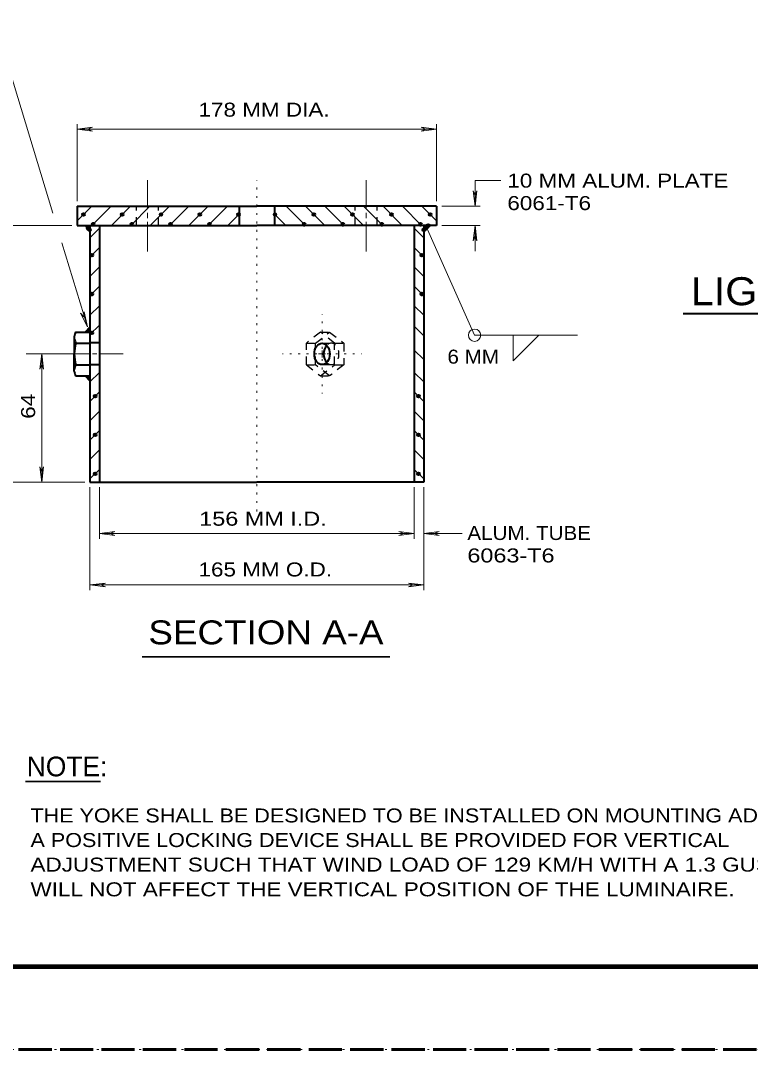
# Model space of a CAD drawing. Extents: x 312583 to 312854, y 144419 to 144597.
# Drawn here: x 312643.1 to 312682.7, y 144418.6 to 144474.4 of the extents above; entities that cross this region are included whole.
import ezdxf
from ezdxf.enums import TextEntityAlignment as Align

# ---------------------------------------------------------------- set-up
doc = ezdxf.new("R2010")
doc.units = 0
doc.header["$LTSCALE"] = 0.3
doc.header["$PDMODE"] = 32
doc.header["$PDSIZE"] = 0.15
for name, pattern in [('DOTTED', [1.5, 0.3, -1.2]), ('LONG_DASHED', [7.5, 6, -1.5]), ('SHORT_DASHED', [2.7, 1.5, -1.2])]:
    doc.linetypes.add(name, pattern=pattern)
for name, color, linetype, lineweight in [('1', 7, 'Continuous', 40), ('2', 7, 'Continuous', 13), ('63', 7, 'DOTTED', 13)]:
    doc.layers.add(name, color=color, linetype=linetype, lineweight=lineweight)

msp = doc.modelspace()

# ---------------------------------------------------------------- linework, layer by layer
at = {"layer": '1', "linetype": 'DOTTED', "lineweight": 13}
msp.add_line((312655.8787, 144447.7894), (312655.8787, 144465.7601), dxfattribs=at)
at = {"layer": '1'}
for p, q in [((312646.1267, 144464.3571), (312655.8787, 144464.3571)), ((312646.1267, 144464.3571), (312646.1267, 144463.3144)), ((312654.9204, 144464.3571), (312654.9204, 144463.3144)), ((312665.6384, 144464.3571), (312655.8787, 144464.3571)), ((312656.8447, 144464.3571), (312656.8447, 144463.3144)), ((312665.6384, 144464.3571), (312665.6384, 144463.3144)), ((312646.1267, 144463.3144), (312655.8787, 144463.3144)), ((312647.3381, 144463.3144), (312647.3381, 144449.3764)), ((312665.6384, 144463.3144), (312655.8787, 144463.3144)), ((312664.4194, 144463.3144), (312664.4194, 144449.3764)), ((312645.9734, 144457.2654), (312645.9734, 144456.3454)), ((312646.0577, 144457.5261), (312646.8167, 144457.5261)), ((312646.0654, 144456.9281), (312646.8167, 144456.9281)), ((312647.3381, 144456.9434), (312646.8167, 144456.9434)), ((312645.9734, 144455.4101), (312645.9734, 144456.3684)), ((312646.0577, 144455.7474), (312646.8167, 144455.7474)), ((312647.3381, 144455.7474), (312646.8167, 144455.7474)), ((312646.0577, 144455.1494), (312646.8167, 144455.1494)), ((312646.8167, 144449.3764), (312655.8787, 144449.3764)), ((312664.9407, 144449.3764), (312655.8787, 144449.3764))]:
    msp.add_line(p, q, dxfattribs=at)
at = {"layer": '1', "lineweight": 25}
for p, q in [((312646.1267, 144463.5597), (312646.9241, 144464.3571)), ((312646.9317, 144463.3144), (312647.9821, 144464.3571)), ((312647.9897, 144463.3144), (312649.0324, 144464.3571)), ((312649.0401, 144463.3144), (312650.0827, 144464.3571)), ((312650.0981, 144463.3144), (312651.1407, 144464.3571)), ((312651.1407, 144463.3144), (312652.1911, 144464.3571)), ((312652.1987, 144463.3144), (312653.2414, 144464.3571)), ((312653.2491, 144463.3144), (312654.2917, 144464.3571)), ((312654.2994, 144463.3144), (312654.9204, 144463.9277)), ((312657.4581, 144463.3144), (312656.8447, 144463.9277)), ((312658.5161, 144463.3144), (312657.4657, 144464.3571)), ((312659.5664, 144463.3144), (312658.5161, 144464.3571)), ((312660.6167, 144463.3144), (312659.5741, 144464.3571)), ((312661.6671, 144463.3144), (312660.6244, 144464.3571)), ((312662.7251, 144463.3144), (312661.6747, 144464.3571)), ((312663.7754, 144463.3144), (312662.7327, 144464.3571)), ((312664.8257, 144463.3144), (312663.7831, 144464.3571)), ((312665.6384, 144463.5597), (312664.8334, 144464.3571)), ((312646.8167, 144462.6474), (312647.3381, 144463.1687)), ((312664.9407, 144462.6474), (312664.4194, 144463.1687)), ((312646.8167, 144461.5971), (312647.3381, 144462.1184)), ((312664.9407, 144461.5971), (312664.4194, 144462.1184)), ((312646.8167, 144460.5467), (312647.3381, 144461.0681)), ((312664.9407, 144460.5467), (312664.4194, 144461.0681)), ((312646.8167, 144459.4964), (312647.3381, 144460.0101)), ((312664.9407, 144459.4964), (312664.4194, 144460.0101)), ((312646.8167, 144458.4384), (312647.3381, 144458.9597)), ((312664.9407, 144458.4384), (312664.4194, 144458.9597)), ((312646.5407, 144457.5261), (312646.8167, 144457.8097)), ((312646.8167, 144457.3881), (312647.3381, 144457.9094)), ((312664.9561, 144457.3037), (312664.4347, 144457.8327)), ((312664.9484, 144456.0311), (312664.4271, 144456.5524)), ((312646.8167, 144454.8197), (312647.3381, 144455.3334)), ((312664.9407, 144454.8197), (312664.4194, 144455.3334)), ((312646.8167, 144453.7617), (312647.3381, 144454.2831)), ((312664.9407, 144453.7617), (312664.4194, 144454.2831)), ((312646.8167, 144452.7114), (312647.3381, 144453.2327)), ((312664.9407, 144452.7114), (312664.4194, 144453.2327)), ((312646.8167, 144451.6611), (312647.3381, 144452.1824)), ((312664.9407, 144451.6611), (312664.4194, 144452.1824)), ((312646.8167, 144450.6031), (312647.3381, 144451.1321)), ((312664.9407, 144450.6031), (312664.4194, 144451.1321)), ((312646.8167, 144449.5527), (312647.3381, 144450.0741)), ((312664.9407, 144449.5527), (312664.4194, 144450.0741))]:
    msp.add_line(p, q, dxfattribs=at)
at = {"layer": '1', "linetype": 'SHORT_DASHED', "lineweight": 25}
for p, q in [((312649.3467, 144463.3144), (312649.3467, 144464.3571)), ((312650.5427, 144463.3144), (312650.5427, 144464.3571)), ((312661.2224, 144463.3144), (312661.2224, 144464.3571)), ((312662.4184, 144463.3144), (312662.4184, 144464.3571)), ((312659.3287, 144457.5261), (312659.8347, 144457.5261)), ((312658.5697, 144455.7474), (312658.5697, 144456.9281)), ((312658.5697, 144456.9281), (312659.0681, 144456.9281)), ((312659.4207, 144456.9204), (312659.9267, 144456.9204)), ((312660.1031, 144455.7474), (312660.1031, 144456.9281)), ((312660.1031, 144456.9281), (312660.6014, 144456.9281)), ((312658.5697, 144455.7474), (312659.3287, 144455.1494)), ((312658.5697, 144455.7474), (312659.0681, 144455.7474)), ((312659.3287, 144455.1494), (312660.1031, 144455.7474)), ((312659.4207, 144455.7627), (312659.9267, 144455.7627)), ((312660.1031, 144455.7474), (312660.6014, 144455.7474)), ((312659.3287, 144455.1494), (312659.8347, 144455.1494))]:
    msp.add_line(p, q, dxfattribs=at)
at = {"layer": '1', "lineweight": 35}
for p, q in [((312646.5714, 144463.2837), (312646.5944, 144463.3144)), ((312646.6557, 144463.1994), (312646.7784, 144463.3144)), ((312665.1017, 144463.1994), (312664.9867, 144463.3144)), ((312665.1477, 144463.2454), (312665.0787, 144463.3144)), ((312665.1937, 144463.2837), (312665.1631, 144463.3144)), ((312646.7017, 144463.1534), (312646.8167, 144463.2684)), ((312646.7477, 144463.1074), (312646.8167, 144463.1764)), ((312646.7937, 144463.0614), (312646.8167, 144463.0844)), ((312665.0557, 144463.1534), (312664.9407, 144463.2684)), ((312665.0097, 144463.1074), (312664.9407, 144463.1764)), ((312664.9637, 144463.0614), (312664.9407, 144463.0844)), ((312646.6174, 144457.5261), (312646.8167, 144457.7254)), ((312646.7094, 144457.5261), (312646.8167, 144457.6334)), ((312646.8014, 144457.5261), (312646.8167, 144457.5491)), ((312646.5637, 144455.1187), (312646.5944, 144455.1494)), ((312646.6097, 144455.0804), (312646.6864, 144455.1494)), ((312646.6557, 144455.0267), (312646.7707, 144455.1494)), ((312646.7017, 144454.9884), (312646.8167, 144455.1034)), ((312646.7477, 144454.9424), (312646.8167, 144455.0114)), ((312646.7937, 144454.8964), (312646.8167, 144454.9271))]:
    msp.add_line(p, q, dxfattribs=at)
at = {"layer": '1', "lineweight": 158}
msp.add_line((312616.5, 144423.0846), (312849, 144423.0846), dxfattribs=at)
at = {"layer": '1', "lineweight": 25}
for points in [[(312646.8167, 144463.3144), (312646.5407, 144463.3144), (312646.8167, 144463.0384)], [(312664.9407, 144463.3144), (312665.2167, 144463.3144), (312664.9407, 144463.0384)], [(312646.5407, 144457.5261), (312646.8167, 144457.5261), (312646.8167, 144457.8097)], [(312646.8167, 144455.1494), (312646.5407, 144455.1494), (312646.8167, 144454.8657)]]:
    msp.add_lwpolyline(points, close=True, dxfattribs=at)
at = {"layer": '1'}
for points in [[(312646.8167, 144463.3144), (312646.8167, 144456.3454), (312646.8167, 144449.3764)], [(312664.9407, 144463.3144), (312664.9407, 144456.3454), (312664.9407, 144449.3764)]]:
    msp.add_lwpolyline(points, dxfattribs=at)
at = {"layer": '1', "linetype": 'SHORT_DASHED', "lineweight": 25}
msp.add_lwpolyline([(312660.1031, 144456.9281), (312659.3287, 144457.5261), (312658.5697, 144456.9281)], dxfattribs=at)
msp.add_lwpolyline([(312659.8347, 144457.5261), (312660.6014, 144456.9281), (312660.6014, 144455.7474), (312659.8347, 144455.1494), (312659.0681, 144455.7474), (312659.0681, 144456.9281)], close=True, dxfattribs=at)
at = {"layer": '1'}
for centre, radius, start, end in [((312646.466, 144457.2541), 0.4914, 145.8703, 178.33743), ((312647.351, 144457.4914), 1.4072, 192.17822, 203.35152), ((312648.5123, 144456.276), 2.5396, 164.99798, 178.595), ((312648.5123, 144456.4005), 2.5396, 181.405, 195.00202), ((312647.351, 144455.1851), 1.4072, 156.63419, 167.82178), ((312646.466, 144455.4224), 0.4914, 181.66257, 214.1297)]:
    msp.add_arc(centre, radius, start, end, dxfattribs=at)
msp.add_ellipse((312659.4214, 144456.3398), major_axis=(0, -0.5799), ratio=0.721154, dxfattribs=at)
msp.add_ellipse((312659.9232, 144456.3398), major_axis=(0, -0.5799), ratio=0.721154, start_param=3.7862494, end_param=5.6396842, dxfattribs=at)
at = {"layer": '1', "linetype": 'SHORT_DASHED', "lineweight": 25}
msp.add_ellipse((312659.9232, 144456.3398), major_axis=(0, -0.5799), ratio=0.721154, start_param=5.6396842, end_param=10.0694347, dxfattribs=at)
at = {"layer": '1'}
for p in [(312646.4717, 144463.9047), (312648.5724, 144463.9047), (312650.6807, 144463.9047), (312652.7891, 144463.9047), (312654.8897, 144463.9047), (312656.8677, 144463.9047), (312658.9761, 144463.9047), (312661.0767, 144463.9047), (312663.1851, 144463.9047), (312665.2934, 144463.9047), (312646.9931, 144463.3757), (312649.1014, 144463.3757), (312651.2021, 144463.3757), (312653.3104, 144463.3757), (312658.4471, 144463.3757), (312660.5554, 144463.3757), (312662.6637, 144463.3757), (312664.7644, 144463.3757), (312665.0864, 144463.2147), (312665.1324, 144463.2607), (312665.1784, 144463.3067), (312646.7247, 144463.1687), (312646.7707, 144463.1227), (312646.8091, 144463.0767), (312664.9484, 144463.0767), (312664.9944, 144463.1227), (312665.0404, 144463.1687), (312646.9241, 144461.6967), (312664.8411, 144461.6967), (312646.9241, 144459.5961), (312664.8411, 144459.5961), (312646.9241, 144457.4877), (312647.1081, 144454.0454), (312664.6571, 144454.0454), (312647.1081, 144451.9447), (312664.6571, 144451.9447), (312647.1081, 144449.8364), (312664.6571, 144449.8364)]:
    msp.add_point(p, dxfattribs=at)
at = {"layer": '2'}
for p, q in [((312644.8159, 144463.9808), (312639.6916, 144480.8177)), ((312646.1267, 144464.6407), (312646.1267, 144468.8191)), ((312646.1267, 144468.5431), (312646.9624, 144468.6427)), ((312646.1267, 144468.5431), (312665.6384, 144468.5431)), ((312646.1267, 144468.5431), (312646.9624, 144468.4357)), ((312646.9624, 144468.6427), (312646.6941, 144468.5431)), ((312646.9624, 144468.4357), (312646.6941, 144468.5431)), ((312664.8027, 144468.6427), (312665.0634, 144468.5431)), ((312665.6384, 144468.5431), (312664.8027, 144468.6427)), ((312664.8027, 144468.4357), (312665.0634, 144468.5431)), ((312665.6384, 144468.5431), (312664.8027, 144468.4357)), ((312665.6384, 144464.6407), (312665.6384, 144468.8191)), ((312649.9447, 144464.1961), (312649.9447, 144465.7677)), ((312661.8204, 144464.1961), (312661.8204, 144465.7677)), ((312667.7314, 144464.3571), (312667.7314, 144465.7524)), ((312669.1267, 144465.7524), (312667.7314, 144465.7524)), ((312667.6241, 144465.2004), (312667.7314, 144464.9321)), ((312667.7314, 144464.3571), (312667.6241, 144465.2004)), ((312667.8311, 144465.2004), (312667.7314, 144464.9321)), ((312667.7314, 144464.3571), (312667.8311, 144465.2004)), ((312649.9447, 144463.7054), (312649.9447, 144463.9967)), ((312661.8204, 144463.7054), (312661.8204, 144463.9967)), ((312665.9144, 144464.3571), (312668.0074, 144464.3571)), ((312645.8431, 144463.3144), (312640.6365, 144463.3144)), ((312649.9447, 144463.5061), (312649.9447, 144461.9037)), ((312661.8204, 144463.5061), (312661.8204, 144461.9037)), ((312665.9144, 144463.3144), (312668.0074, 144463.3144)), ((312667.7314, 144463.3144), (312667.6241, 144462.4787)), ((312667.7314, 144461.9191), (312667.7314, 144463.3144)), ((312667.7314, 144463.3144), (312667.8311, 144462.4787)), ((312667.6241, 144462.4787), (312667.7314, 144462.7471)), ((312667.8311, 144462.4787), (312667.7314, 144462.7471)), ((312646.6941, 144457.8097), (312645.3042, 144462.3765)), ((312646.3107, 144458.5611), (312646.4947, 144458.3464)), ((312646.6941, 144457.8097), (312646.3107, 144458.5611)), ((312646.5024, 144458.6301), (312646.4947, 144458.3464)), ((312646.6941, 144457.8097), (312646.5024, 144458.6301)), ((312646.8014, 144456.3454), (312643.3649, 144456.3454)), ((312644.205, 144456.3454), (312644.0977, 144455.5097)), ((312644.205, 144449.3764), (312644.205, 144456.3454)), ((312644.205, 144456.3454), (312644.3047, 144455.5097)), ((312647.1924, 144456.3454), (312646.9547, 144456.3454)), ((312647.3534, 144456.3454), (312648.6337, 144456.3454)), ((312659.4207, 144456.3377), (312659.2367, 144456.3377)), ((312659.4207, 144456.3377), (312659.4207, 144456.5294)), ((312659.4207, 144456.3377), (312659.6047, 144456.3377)), ((312659.4207, 144456.3377), (312659.4207, 144456.1537)), ((312644.0977, 144455.5097), (312644.205, 144455.7704)), ((312644.3047, 144455.5097), (312644.205, 144455.7704)), ((312644.0977, 144450.2121), (312644.205, 144449.9437)), ((312644.205, 144449.3764), (312644.0977, 144450.2121)), ((312644.3047, 144450.2121), (312644.205, 144449.9437)), ((312644.205, 144449.3764), (312644.3047, 144450.2121)), ((312646.5407, 144449.3764), (312640.6365, 144449.3764)), ((312646.8167, 144449.1004), (312646.8167, 144443.5191)), ((312647.3381, 144449.1004), (312647.3381, 144446.3097)), ((312664.4194, 144449.1004), (312664.4194, 144446.3097)), ((312664.9407, 144449.1004), (312664.9407, 144443.5191)), ((312647.3381, 144446.5857), (312648.1814, 144446.6931)), ((312647.3381, 144446.5857), (312664.4194, 144446.5857)), ((312647.3381, 144446.5857), (312648.1814, 144446.4861)), ((312648.1814, 144446.6931), (312647.9131, 144446.5857)), ((312648.1814, 144446.4861), (312647.9131, 144446.5857)), ((312663.5837, 144446.6931), (312663.8521, 144446.5857)), ((312664.4194, 144446.5857), (312663.5837, 144446.6931)), ((312663.5837, 144446.4861), (312663.8521, 144446.5857)), ((312664.4194, 144446.5857), (312663.5837, 144446.4861)), ((312664.9407, 144446.5857), (312665.7841, 144446.6931)), ((312664.9407, 144446.5857), (312667.0337, 144446.5857)), ((312664.9407, 144446.5857), (312665.7841, 144446.4861)), ((312665.7841, 144446.6931), (312665.5157, 144446.5857)), ((312665.7841, 144446.4861), (312665.5157, 144446.5857)), ((312646.8167, 144443.8027), (312647.6601, 144443.9024)), ((312646.8167, 144443.8027), (312664.9407, 144443.8027)), ((312646.8167, 144443.8027), (312647.6601, 144443.6954)), ((312647.6601, 144443.9024), (312647.3917, 144443.8027)), ((312647.6601, 144443.6954), (312647.3917, 144443.8027)), ((312664.1051, 144443.9024), (312664.3734, 144443.8027)), ((312664.9407, 144443.8027), (312664.1051, 144443.9024)), ((312664.1051, 144443.6954), (312664.3734, 144443.8027)), ((312664.9407, 144443.8027), (312664.1051, 144443.6954))]:
    msp.add_line(p, q, dxfattribs=at)
at = {"layer": '2', "linetype": 'DOTTED'}
for p, q in [((312659.4207, 144456.6214), (312659.4207, 144458.4767)), ((312659.1447, 144456.3377), (312657.2817, 144456.3377)), ((312659.4207, 144456.0617), (312659.4207, 144454.1987)), ((312659.7044, 144456.3377), (312661.5597, 144456.3377))]:
    msp.add_line(p, q, dxfattribs=at)
at = {"layer": '2', "lineweight": 40}
msp.add_line((312679.0175, 144458.5382), (312716.0815, 144458.5382), dxfattribs=at)
at = {"layer": '2', "lineweight": 35}
for p, q in [((312649.6533, 144439.9004), (312663.0931, 144439.9004)), ((312643.3216, 144433.1266), (312647.4002, 144433.1266))]:
    msp.add_line(p, q, dxfattribs=at)
at = {"layer": '2'}
for points in [[(312665.1401, 144463.0921), (312667.7007, 144457.3574), (312673.2821, 144457.3574)], [(312671.1891, 144457.3574), (312669.7937, 144455.9621), (312669.7937, 144457.3574)]]:
    msp.add_lwpolyline(points, dxfattribs=at)
msp.add_circle((312667.7042, 144457.3546), 0.3332, dxfattribs=at)
at = {"layer": '63', "linetype": 'LONG_DASHED', "lineweight": 60}
msp.add_line((312851.75, 144418.5846), (312583.526, 144418.5846), dxfattribs=at)
at = {"layer": '63'}
msp.add_lwpolyline([(312601.2, 144418.5846), (312853.5, 144418.5846), (312853.5, 144596.7846)], dxfattribs=at)

# ---------------------------------------------------------------- texts
at = {"layer": '2'}
for s, width, p in [('178 MM DIA.', 1.2, (312652.7155, 144469.2207)), ('10 MM ALUM. PLATE', 1.2, (312669.4794, 144465.3681)), ('6061-T6', 1.2, (312669.4794, 144464.1481)), ('6 MM', 1.1, (312666.2283, 144455.8121)), ('156 MM I.D.', 1.25, (312652.7549, 144447.0151)), ('ALUM. TUBE', 1.1, (312667.3097, 144446.2397)), ('6063-T6', 1.25, (312667.3097, 144445.0197)), ('165 MM O.D.', 1.2, (312652.7146, 144444.2599)), ('THE YOKE SHALL BE DESIGNED TO BE INSTALLED ON MOUNTING ADAPTER.', 1.15, (312643.5976, 144430.9051)), ('A POSITIVE LOCKING DEVICE SHALL BE PROVIDED FOR VERTICAL', 1.15, (312643.5976, 144429.5711)), ('ADJUSTMENT SUCH THAT WIND LOAD OF 129 KM/H WITH A 1.3 GUST FACTOR ', 1.2, (312643.5976, 144428.2371)), ('WILL NOT AFFECT THE VERTICAL POSITION OF THE LUMINAIRE.', 1.2, (312643.5976, 144426.8954))]:
    msp.add_text(s, height=0.76, dxfattribs=dict(at, width=width)).set_placement(p)
for s, height, width, p in [('LIGHTING STANDARD ASSEMBLY', 1.52, 1.1, (312697.5179, 144458.9849)), ('SECTION A-A', 1.299, 1.15, (312656.377, 144440.5751))]:
    msp.add_text(s, height=height, dxfattribs=dict(at, width=width)).set_placement(p, align=Align.CENTER)
at = {"layer": '2', "width": 1.2}
msp.add_text('64 ', height=0.76, rotation=90, dxfattribs=at).set_placement((312643.847, 144452.8199))
at = {"layer": '2'}
msp.add_text('NOTE:', height=1.07, dxfattribs=at).set_placement((312645.5819, 144433.4099), align=Align.CENTER)

doc.saveas('drawing.dxf')
